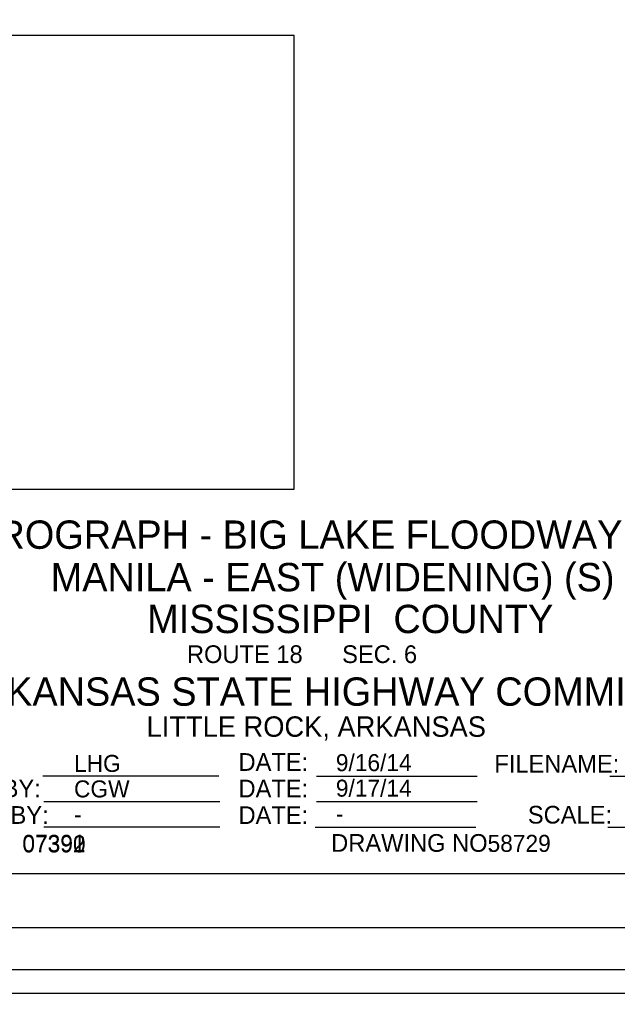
# Model space of a CAD drawing. Extents: x -1063117.9 to -1063075.9, y -253323.6 to -253301.6.
# Drawn here: x -1063089.9 to -1063085.67, y -253323.61 to -253316.73 of the extents above; entities that cross this region are included whole.
import ezdxf

# ---------------------------------------------------------------- set-up
doc = ezdxf.new("R2010")
doc.units = 0
for name, color, linetype in [('border', 7, 'Continuous'), ('Border 2660-Hwy18 - Level 62', 7, 'Continuous'), ('Border 2660-Hwy18 - Level 63', 7, 'Continuous'), ('Border 2660-Hwy18 - Text', 7, 'Continuous'), ('Border 2660-Hwy18 - Title Text', 7, 'Continuous'), ('Bridge No BLFR', 7, 'Continuous'), ('Bridge No BLO', 7, 'Continuous'), ('Bridge No Ditch 81', 7, 'Continuous'), ('Dimensions', 7, 'Continuous'), ('Level 62 PDF', 7, 'Continuous'), ('Text', 7, 'Continuous'), ('Title Block Text', 7, 'Continuous'), ('Title Text', 7, 'Continuous')]:
    doc.layers.add(name, color=color, linetype=linetype)

msp = doc.modelspace()

# ---------------------------------------------------------------- linework, layer by layer
at = {"layer": 'border'}
for p, q in [((-1063089.7331, -253322.0701), (-1063088.4899, -253322.0701)), ((-1063087.7999, -253322.0712), (-1063086.666, -253322.0712)), ((-1063085.73, -253322.0712), (-1063084.3939, -253322.0712)), ((-1063089.7259, -253322.2501), (-1063088.4827, -253322.2501)), ((-1063087.7999, -253322.2512), (-1063086.666, -253322.2512)), ((-1063089.7259, -253322.4301), (-1063088.4827, -253322.4301)), ((-1063087.8107, -253322.4312), (-1063086.6768, -253322.4312)), ((-1063085.7424, -253322.4312), (-1063084.5768, -253322.4312)), ((-1063084.146, -253322.7613), (-1063116.1571, -253322.7613))]:
    msp.add_line(p, q, dxfattribs=at)
at = {"layer": 'Border 2660-Hwy18 - Level 62'}
msp.add_lwpolyline([(-1063117.7772, -253301.6304), (-1063083.6588, -253301.6304), (-1063083.6588, -253323.4399), (-1063117.7772, -253323.4399)], close=True, dxfattribs=at)
at = {"layer": 'Border 2660-Hwy18 - Level 63'}
msp.add_lwpolyline([(-1063117.8883, -253301.7733), (-1063083.8888, -253301.7733), (-1063083.8888, -253323.1428), (-1063117.8883, -253323.1428)], close=True, dxfattribs=at)
at = {"layer": 'Dimensions'}
msp.add_lwpolyline([(-1063099.4515, -253320.046), (-1063087.958, -253320.046), (-1063087.958, -253316.8434), (-1063099.4515, -253316.8434)], close=True, dxfattribs=at)
at = {"layer": 'Level 62 PDF'}
msp.add_lwpolyline([(-1063117.5272, -253301.797), (-1063083.4088, -253301.797), (-1063083.4088, -253323.6065), (-1063117.5272, -253323.6065)], close=True, dxfattribs=at)

# ---------------------------------------------------------------- texts
at = {"layer": 'Border 2660-Hwy18 - Text'}
for s, p in [('DATE:', (-1063088.3519, -253322.0346)), ('FILENAME:', (-1063086.545, -253322.0467)), ('CHECKED BY:', (-1063090.8815, -253322.2211)), ('DATE:', (-1063088.3519, -253322.2221)), ('DESIGNED BY:', (-1063090.8815, -253322.4086)), ('DATE:', (-1063088.3519, -253322.4096)), ('SCALE:', (-1063086.3084, -253322.4067)), ('DRAWING NO.', (-1063087.6976, -253322.606))]:
    msp.add_text(s, height=0.125, dxfattribs=at).set_placement(p)
at = {"layer": 'Border 2660-Hwy18 - Title Text'}
for s, height, p in [('MISSISSIPPI  COUNTY', 0.199999, (-1063088.9969, -253321.0622)), ('ROUTE 18      SEC. 6', 0.125, (-1063088.7161, -253321.2733)), ('ARKANSAS STATE HIGHWAY COMMISSION', 0.199999, (-1063090.3573, -253321.5749)), ('LITTLE ROCK, ARKANSAS', 0.144, (-1063089.0011, -253321.7941))]:
    msp.add_text(s, height=height, dxfattribs=at).set_placement(p)
at = {"layer": 'Bridge No BLFR'}
msp.add_text('07392', height=0.12, dxfattribs=at).set_placement((-1063089.8782, -253322.6106))
at = {"layer": 'Bridge No BLO'}
msp.add_text('07391', height=0.12, dxfattribs=at).set_placement((-1063089.8782, -253322.6061))
at = {"layer": 'Bridge No Ditch 81'}
msp.add_text('07390', height=0.12, dxfattribs=at).set_placement((-1063089.8782, -253322.6106))
at = {"layer": 'Text'}
for s, p in [('LHG', (-1063089.5136, -253322.042)), ('9/16/14', (-1063087.6644, -253322.0367)), ('CGW', (-1063089.5136, -253322.222)), ('9/17/14', (-1063087.6644, -253322.2167)), ('-', (-1063089.5136, -253322.402)), ('-', (-1063087.6644, -253322.3967))]:
    msp.add_text(s, height=0.12, dxfattribs=at).set_placement(p)
at = {"layer": 'Title Block Text'}
msp.add_text('58729', height=0.12, dxfattribs=at).set_placement((-1063086.5928, -253322.6064))
at = {"layer": 'Title Text'}
for s, p in [('HYDROGRAPH - BIG LAKE FLOODWAY RELIEF', (-1063090.6187, -253320.467)), ('MANILA - EAST (WIDENING) (S)', (-1063089.6783, -253320.767))]:
    msp.add_text(s, height=0.199999, dxfattribs=at).set_placement(p)

doc.saveas('drawing.dxf')
